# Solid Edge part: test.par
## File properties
Title: Thrust bearing
Author: Abhinav Rai
Template: Normal.par
Last saved by: Rajat Kamboj
Revision: 13
Application: Solid Edge
Accuracy: 0.99
Material: aluminum
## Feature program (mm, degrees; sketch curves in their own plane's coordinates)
sketch for "unnamed RevolvedProtrusion 1" plane through (0, 0, 0) normal (0, -1, 0) x-axis (1, 0, 0)
  line (47.625, 16.8036) -> (66.929, 16.8036)
  line (66.929, 16.8036) -> (73.025, 10.7076)
  line (73.025, 10.7076) -> (73.025, -12.0254)
  line (73.025, -12.0254) -> (66.929, -18.1214)
  line (66.929, -18.1214) -> (47.625, -18.1214)
  line (47.625, -18.1214) -> (47.625, -7.1994)
  line (61.5714, -7.1994) -> (47.625, -7.1994)
  line (61.5714, 5.8816) -> (61.5714, -7.1994)
  line (47.625, 5.8816) -> (61.5714, 5.8816)
  line (47.625, 5.8816) -> (47.625, 16.8036)
revolve "unnamed RevolvedProtrusion 1" add finite 360 deg
sketch for "unnamed RevolvedProtrusion 2" plane through (0, 0, 0) normal (1, 0, 0) x-axis (0, 1, 0)
  line (69.977, 13.7556) -> (73.0652, 13.7556)
  line (73.0652, 13.7556) -> (74.6125, 12.2083)
  line (74.6125, 12.2083) -> (74.6125, -13.4669)
  line (74.6125, -13.4669) -> (73.006, -15.0734)
  line (73.006, -15.0734) -> (69.977, -15.0734)
revolve "unnamed RevolvedProtrusion 2" add full turn 360 deg
sketch for "unnamed RevolvedProtrusion 3" plane through (0, 0, 0) normal (0, -1, 0) x-axis (1, 0, 0)
revolve "unnamed RevolvedProtrusion 3" add full turn 360 deg about sketch line (-54.9674, 10.1232) -> (-54.9674, -18.1214)
pattern "unnamed Pattern 1" of "unnamed RevolvedProtrusion 3"
pattern "unnamed Pattern 2"
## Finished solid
Body 1: solid body, 39 faces, 39 edges, 25 vertices.
  Faces by surface: torus 25, plane 6, cone 4, cylinder 4
  Edges by curve: circle 39
Bounding box of the edges (mm; curved faces can reach further): 149.225 x 149.225 x 34.925, from (-74.6125, -74.6125, -18.1214) to (74.6125, 74.6125, 16.8036).
Cylindrical faces by radius (mm): R47.625 x2, R61.5714 x1, R74.6125 x1
Conical faces (half-angle, radius in mm at the cone's reference point): 45 deg R66.929 x1, 45 deg R73.025 x1, 45 deg R73.0652 x1, 45 deg R74.6125 x1
Toroidal faces (ring radius, tube radius in mm): R-0.1023 r6.604 x25
Planar faces by outward normal: +z 3, -z 3
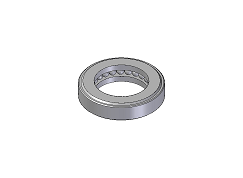
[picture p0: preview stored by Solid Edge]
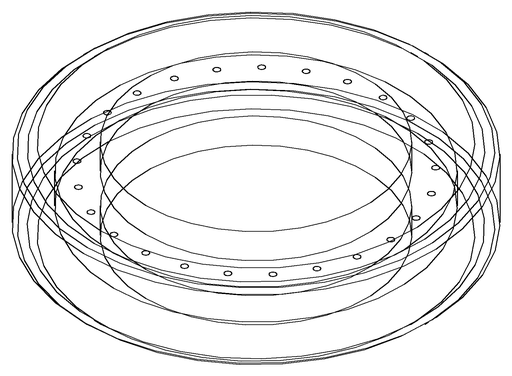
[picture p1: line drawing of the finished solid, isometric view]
